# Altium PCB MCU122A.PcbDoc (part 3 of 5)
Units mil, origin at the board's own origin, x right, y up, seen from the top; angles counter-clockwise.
Board outline 4950 x 3450 mil, 4 copper layers (Top Layer, Signal Layer 1, Signal Layer 2, Bottom Layer), stack 60 mil thick; 257 components, 158 nets, 848 pads, 1971 vias.
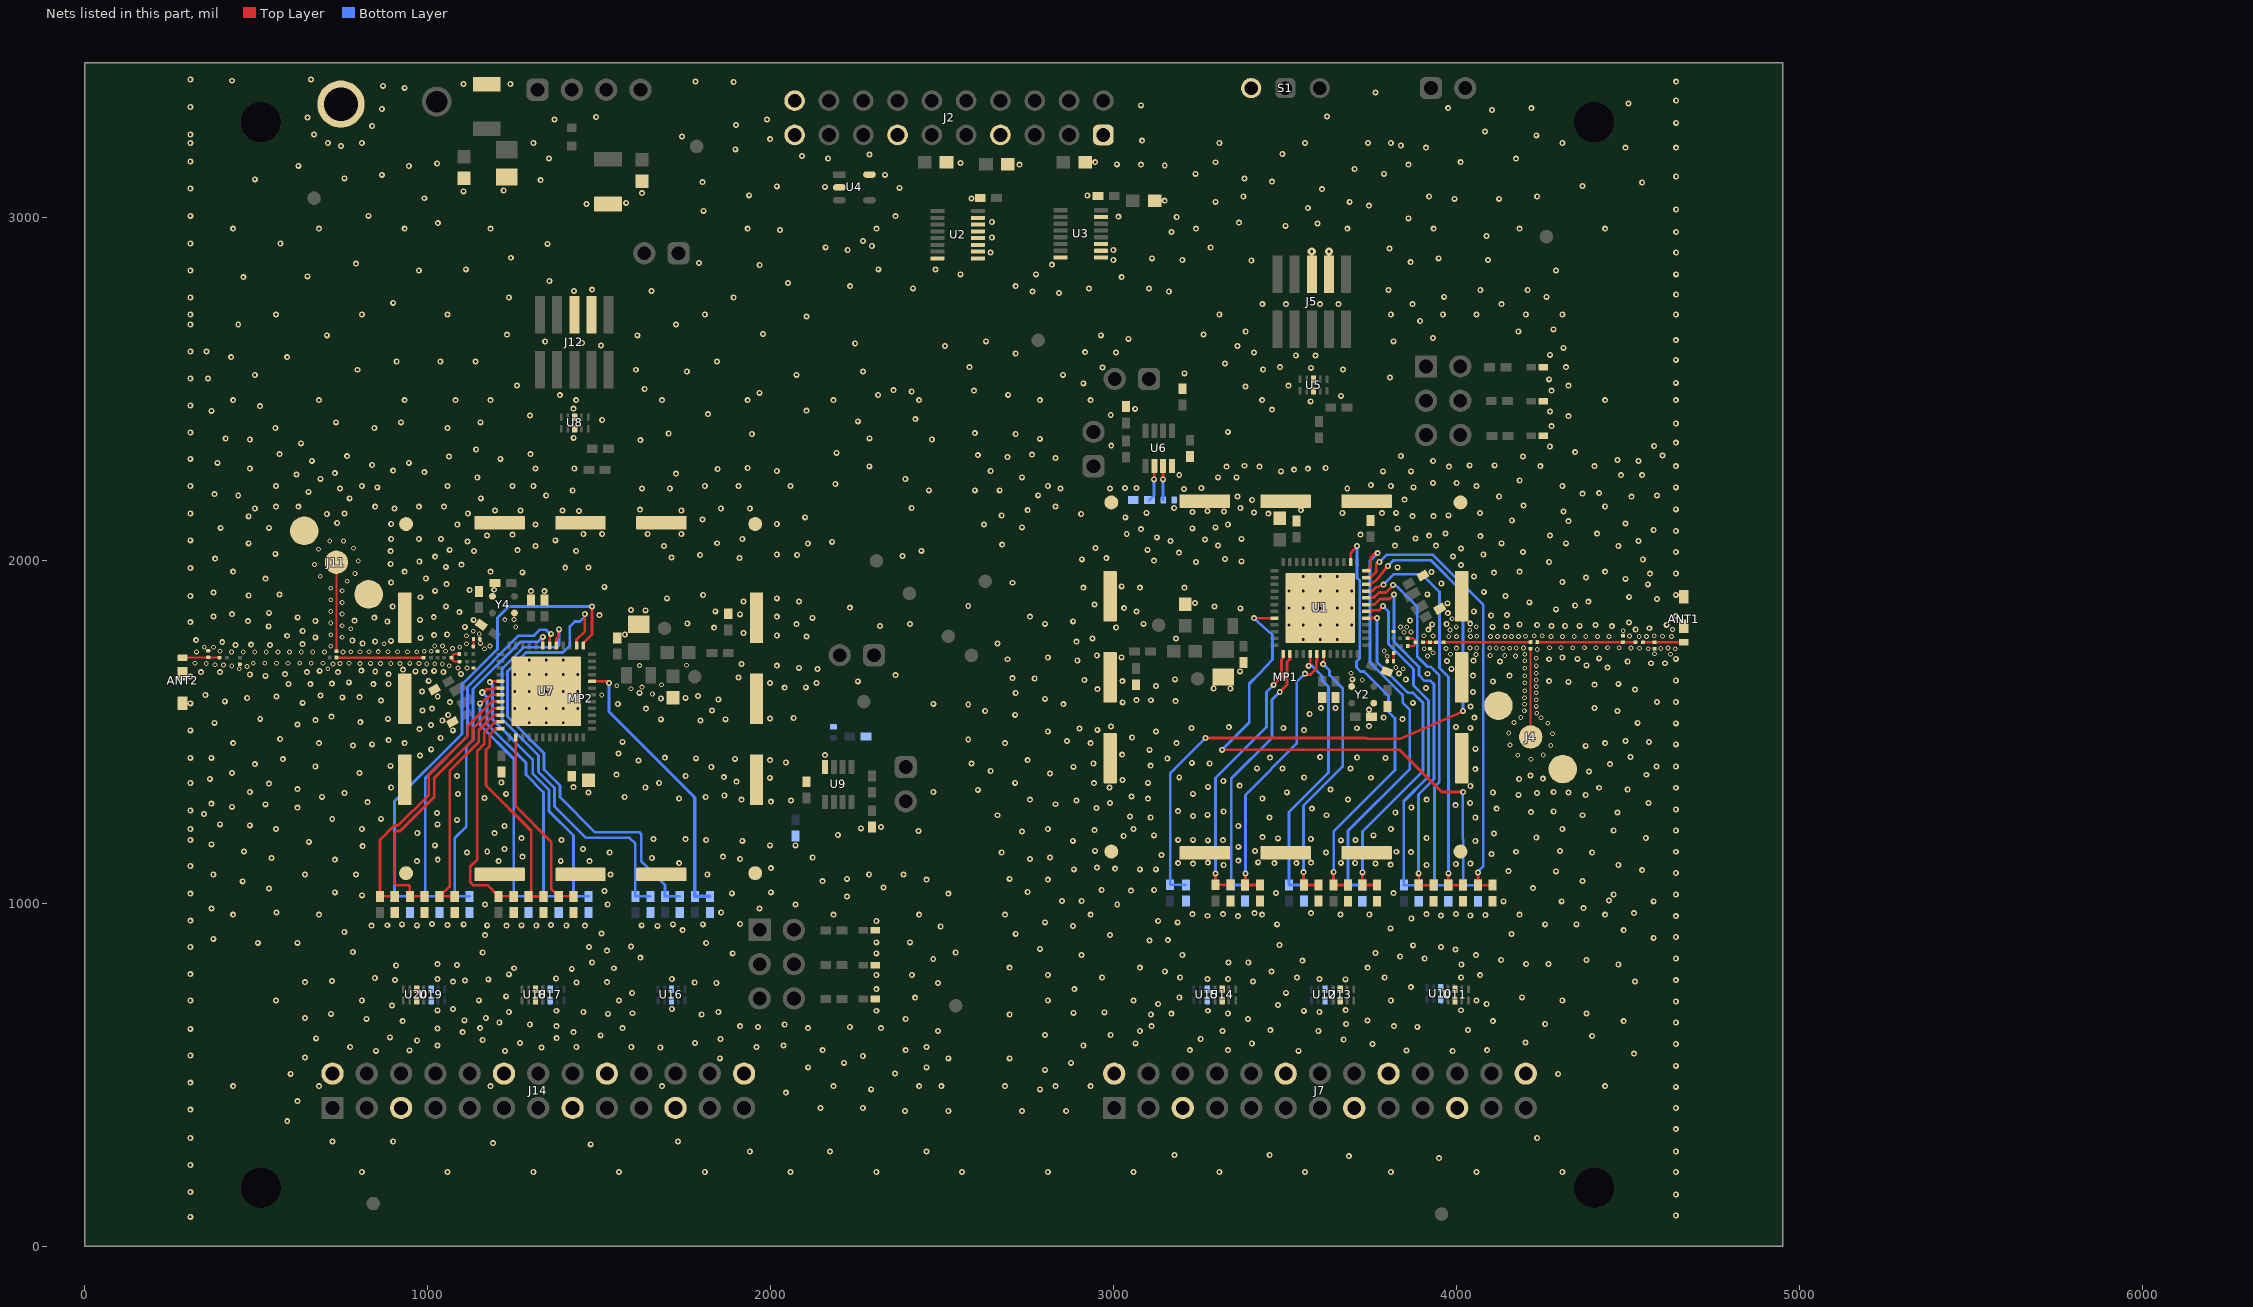
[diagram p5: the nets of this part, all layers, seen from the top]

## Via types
v1: diameter 17.46, hole 8, Top Layer to Bottom Layer, tented both sides, 1708 vias
v2: diameter 13.9, hole 8, Top Layer to Bottom Layer, tented both sides, 206 vias
v3: diameter 19.68, hole 8, Top Layer to Bottom Layer, tented both sides, 42 vias
v4: diameter 24, hole 8, Top Layer to Bottom Layer, tented both sides, 8 vias
v5: diameter 19.46, hole 8, Top Layer to Bottom Layer, tented both sides, 6 vias
v6: diameter 34, hole 8, Top Layer to Bottom Layer, tented both sides, 1 vias

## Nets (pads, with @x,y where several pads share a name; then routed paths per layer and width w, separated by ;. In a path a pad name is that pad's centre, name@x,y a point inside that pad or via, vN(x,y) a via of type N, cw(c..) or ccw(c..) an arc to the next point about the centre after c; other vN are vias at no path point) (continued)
GND: ANT1.2 ANT1.3 ANT2.2 ANT2.3 C1.1 C2.2 C3.2 C4.1 C5.2 C6.1 C7.1 C8.1 C9.1 C10.2 C11.2 C12.1 C13.1 C14.1 C15.1 C16.1 C17.2 C18.1 C19.1 C20.1 C21.2 C22.2 C23.2 C24.2 C25.2 C26.2 C27.2 C28.2 C29.1 C30.1 C31.1 C32.1 C33.1 C34.1 C35.2 C36.2 C37.2 C38.2 C40.2 C41.2 C44.1 C45.1 C46.1 C47.1 C48.2 C49.2 C50.2 C51.2 C52.1 C53.1 C54.1 C55.2 C56.1 C57.1 C58.1 C59.1 C60.1 C61.2 C62.2 C63.2 C64.2 C65.2 C66.2 C67.2 C68.2 C69.1 C70.1 C71.1 C72.1 C73.1 C74.1 C75.2 C76.2 C77.2 C78.2 C80.2 C81.2 C84.1 C85.1 C86.1 C87.1 C88.2 C89.2 C90.2 C91.2 D1.1 D2.1 D3.1 D4.1 D5.1 D6.1 J2.1 J2.7 J2.13 J2.19 J2.20 J4.2 J4.3 J5.3 J5.5 J7.2 J7.5 J7.12 J7.15 J7.18 J7.21 J7.26 J11.2 J11.3 J12.3 J12.5 J14.2 J14.5 J14.12 J14.15 J14.18 J14.21 J14.26 MP1.1 MP1.2 MP1.3 MP1.4 MP1.5 MP1.6 MP1.7 MP1.8 MP1.9 MP1.10 MP1.11 MP1.12 MP1.13 MP1.14 MP1.15 MP1.16 MP2.1 MP2.2 MP2.3 MP2.4 MP2.5 MP2.6 MP2.7 MP2.8 MP2.9 MP2.10 MP2.11 MP2.12 MP2.13 MP2.14 MP2.15 MP2.16 R23.1 R24.1 R47.1 R48.1 S1.2 TP3.1 U1.49 U2.8 U2.9 U2.10 U2.11 U2.12 U2.13 U2.14 U2.15 U3.8 U3.9 U3.10 U3.11 U3.15 U4.2 U4.5 U5.3@3582.66,2526.68 U5.8@3582.66,2493.81 U6.4 U7.49 U8.3@1428.4,2416.13 U8.8@1428.4,2383.26 U9.4 U10.3@3953,719.63 U10.8@3953,752.5 U11.3@3995.17,715.83 U11.8@3995.17,748.71 U12.3@3615.99,715.83 U12.8@3615.99,748.71 U13.3@3660.39,715.83 U13.8@3660.39,748.71 U14.3@3316.14,715.83 U14.8@3316.14,748.71 U15.3@3272.4,715.83 U15.8@3272.4,748.71 U16.3@1710.72,715.83 U16.8@1710.72,748.71 U17.3@1357.81,715.83 U17.8@1357.81,748.71 U18.3@1314.16,715.83 U18.8@1314.16,748.71 U19.3@1010.16,715.83 U19.8@1010.16,748.71 U20.3@967.76,715.83 U20.8@967.76,748.71 Y2.2 Y2.4 Y4.2 Y4.4 | length 1.1
  Top Layer w8: C62.2@1552.78,1773.13 C62.2@1553.55,1772.36
  other v1: 308,85.18 4638.91,88.8 4638.91,150.58 308,157.48 808,216 1058,216 1308,216 1558,216 1808,216 2058,216 2308,216 2558,216 2808,216 3058,216 3308,216 3558,216 3808,216 4058,216 4308,216 4638.91,216 308,236.22 3948.46,256.3 3685.58,262.14 3177.35,265.07 3454.83,265.07 1939,275.59 2173,275.59 2454.03,275.59 4638.91,275.59 1475.36,296.56 1190.05,300 722.44,305.12 899.44,305.12 1729.67,305.12 308,314.96 4234.7,314.72 4638.91,340.52 590.55,364.17 2391.73,393.7 2518.02,393.7 2732.98,393.7 2861.51,393.7 308,397.43 4638.91,402.22 2145.12,402.76 2268.53,402.76 620.23,422.44 2044.09,447 2293.05,456.89 2785.43,456.89 4638.91,464.06 433,466 683,466 1183,466 1683,466 2183,466 2433,466 2497.32,466 2683,466 2830.01,466 2933,466 4433,466 308,476.34 600.39,501.97 4296.04,501.66 2362.2,502.76 2799.9,513.67 2109.25,521.13 2454.03,521.13 4638.91,525.28 2213.73,534.3 2875.69,534.3 1851.64,547.34 2518.02,547.34 2696.85,547.34 641.93,549.99 2268.53,553.71 308,555.53 4516.84,560.63 1225.2,568.47 848.95,569.22 3538.57,569.23 3988.26,568.84 3853.57,569.8 946.84,570.62 2151.56,570.89 2393.7,570.89 3222.1,570.89 3333.33,570.89 4089.03,570.89 1332.14,579.17 1678.22,578.63 773.92,580.13 1433.42,580.05 1593.69,580.22 1958.5,580.22 2454.03,580.22 2037.4,584.34 2911.31,584.34 1028.41,584.6 3754.56,589.29 4638.91,589.1 3402.7,590.46 3063.77,590.93 1269.16,591.97 1779.02,591.97 4200.48,593.6 969.21,599.52 1160.15,600.66 3670.52,601.83 3253.58,603.26 1853.68,603.57 674.78,605.5 1376.2,606.07 889.97,608.37 4394.9,612.18 1504.39,614.31 2799.9,615.35 2991.23,615.35 1101.92,623.6 1425.04,623.6 2487.48,626.86 3076.34,626.91 3317.07,626.86 3596.65,626.91 3456.68,629.42 4032.88,630.07 308,633.38 1028.41,634.48 1152.98,635.18 1567.86,635.18 2108.89,635.18 2321.77,635.18 1962.92,638.88 2230.67,638.88 3885.11,639.31 1375.38,640.98 1911,640.98 3110.14,640.87 3817.13,640.87 1297.76,645.78 2040.95,645.78 3677.96,647.32 4258.11,647.32 1208.77,651.91 4638.91,652.02 4105.38,655.39 4486.77,655.39 927.15,655.71 1107.09,658.1 3740.33,657.79 821.93,662.43 2393.7,662.25 3391.47,662.25 641.93,665.05 1169.59,665.05 1798.83,675 2696.85,675 3108.34,675 718.2,676.9 1525.71,676.9 3167.94,677.43 3332.61,678.26 4378.35,678.26 1596.89,678.68 2882.5,680.04 2973.43,681.43 1236.41,682.23 1453.84,682.4 1847.22,682.4 3599.39,682.6 1374.96,685.99 2308,685.99 3274.46,685.99 3554.33,685.87 1028.76,687.32 4012.61,687.45 3676.52,687.76 1073.63,690.88 1711.57,690.86 895.78,701.06 3479.27,702.58 3129.77,705.44 4087.34,705.44 4638.91,712.92 308,716 558,716 808,716 1558,716 2808,716 3058,716 3808,716 4058,716 4308,716 1148.99,716.56 2421.26,724.03 3191.34,724.39 4190.69,725.22 1228.99,727.97 1596.35,737.87 3502.72,738.17 2308,748.71 2885.14,748.71 3866.16,754.7 1841.49,766.9 2487.48,766.9 1434.16,768.31 1778.29,768.31 641.93,769.23 1522.44,769.23 1073.63,770.59 3406.03,771.05 4519.73,771.05 721.1,772.86 1108.5,773.87 4638.91,775.16 904.33,775.59 1028.76,778.28 1176.59,777.69 1711.57,778.28 3273.25,778.23 3333.72,778.23 3676.09,777.51 3599.96,778.8 1374.61,780.34 845.93,781.78 2966.37,783.16 3193.75,782.73 3534.65,782.73 3790.19,782.73 4013.19,783 2308,790.08 2411.42,790.08 2808,790.08 4068.46,789.63 308,792.47 1236.41,792.32 3149.04,800.44 3460.45,800.44 1419.99,808.32 1252.18,809.88 1542.65,809.88 2696.85,811.6 3076.34,811.6 3740.57,811.6 908.09,817.99 1085.3,819.6 4013.67,820.56 4471.38,820.56 1028.46,821.8 4202.54,822.39 4267.89,822.39 1479.43,826.68 3334.42,826.62 3392.35,826.62 3549.98,831.8 4129.9,833.82 4378.35,833.82 2473.93,836.5 3906.67,838.35 4638.91,838.2 1619.93,840.52 3835.25,844.38 2905.86,848.25 3199.93,848.25 4056.53,848.01 1889.27,853.51 2308,853.51 3763.58,854.36 1160.16,855.45 2539.37,855.61 781.81,857.02 1522.44,860.94 3996.34,864.86 2785.43,866.48 1470.01,871.5 308,871.7 3954.3,871.92 1592.96,873.01 3483.44,877.44 3873.04,876.71 1812.03,883.17 504.77,884.1 620.23,884.1 2308,885.41 2406.31,885.41 3104.36,891.05 3157.68,891.68 374.82,895.67 4574.18,898.76 4638.91,900.98 1167.27,906.27 2989.33,906.78 2714.34,910.22 4159.92,909.95 1506.38,911.2 756.81,915.47 1743.25,920.8 4486.77,920.82 3806.99,926.27 2495.69,931.39 2881.5,932.9 835.95,933.9 1229.71,933.84 1458.33,934.14 1670.21,933.72 882.45,935.26 968.95,934.92 1173.53,934.92 1273.75,935.2 1316.7,934.56 1404.05,934.56 1624.01,935.04 1057.98,935.67 1359.66,935.92 925.32,937.86 1104.83,938.13 1715.04,938.13 1802.28,938.13 3476.55,938.07 4258.11,938.07 4349.5,938.07 1012.77,939.14 1911,938.55 2799.49,943.63 3186.48,943.63 308,948.45 2308,947.8 3129.77,947.8 3867.79,955 3362.39,961.82 4638.91,961.78 3273.49,962.95 3954.07,963.62 4039.64,963.62 4083.36,964.87 433,966 683,966 2183,966 2433,966 2683,966 2933,966 3433,966 3661.08,966.49 3745.33,966.49 4183,966 4433,966 3229.59,967.39 3318.53,967.39 3912.09,967.39 3997.7,967.92 3410.68,970.45 3575.37,970.47 4516.84,970.45 558.88,972.2 1855.53,972.2 369.39,984.01 1967.72,984.25 4369.79,985.17 2072.01,995.4 3010.4,995.4 1166.97,995.82 1524.68,995.82 4136.25,1005.16 4306.05,1004.98 4574.18,1004.98 2849.54,1005.95 2906.58,1005.95 4444.16,1007.5 2222.16,1019.14 808.23,1022.63 4457.81,1024.73 4638.91,1024.91 308,1027.25 2518.02,1027.25 1886.65,1028.42 3473.21,1029.16 3815.85,1028.6 729.36,1031.19 2000.39,1031.24 2749.24,1032.07 1515.22,1035.2 3050.19,1035.97 2965.11,1038.31 3117.95,1038.31 537.1,1042.38 4222.44,1043.31 2328.6,1045.03 460.66,1063.31 2151.14,1063.59 4366.63,1064.33 2454.03,1067.98 2808,1067.98 2222.16,1070.68 2696.85,1070.68 374.82,1083.5 641.93,1083.5 790.7,1083.5 1532.84,1083.5 1815.27,1083.5 2287.19,1083.5 2386.9,1083.5 4638.91,1087.36 4289.24,1092.48 4151.36,1092.79 4540.72,1095.96 2883.68,1098.28 3076.01,1098.28 3122.86,1098.28 3004.42,1100.05 2000.39,1101.76 2951.39,1103.58 308,1107.92 3320.51,1110.9 3912.6,1111.03 4471.38,1111.03 3807.43,1111.98 3997.29,1113.52 3231.24,1114.6 3763.5,1115.16 4039.64,1115.46 1733.13,1116.34 3188.12,1116.36 3468.25,1116.36 3532.33,1116.36 3662.17,1117.42 3704.1,1116.6 3274.35,1117.73 3575.33,1117.73 3421.3,1118.6 969.1,1121.98 1206.97,1121.98 1471.73,1121.98 1387.91,1123.08 3363.3,1123.34 729.36,1126.47 1029.31,1126.47 1911,1128.09 2755.93,1128.09 544.79,1131 1653.39,1131 2122.4,1132.69 2814.22,1132.69 1276.68,1135.03 1860.98,1135.03 3139.65,1139.82 4101.31,1142.68 1114.46,1147.48 1530.45,1147.3 2673.48,1147.13 3619.22,1147.13 4394.9,1147.13 3866.93,1148.12 464.51,1150.5 1173.63,1150.5 3823.99,1149.55 4173.42,1149.55 4638.91,1149.55 2945.2,1152.2 3412.08,1151.96 4301.18,1151.57 1223.84,1157.72 1452.73,1157.72 3363.19,1163.94 810.52,1165.81 1020.68,1168.18 1998.03,1168.18 2072.01,1168.18 369.39,1171.26 653.25,1178.32 4054.16,1180.83 1917.13,1181.51 2880.95,1181.51 3274.35,1182.84 3318.48,1183.28 3662.17,1182.72 3704.68,1183.45 308,1184.06 1390.19,1184.06 1812.03,1184.06 3188.12,1184.45 3231.1,1184.45 1751.96,1186.09 1658.63,1186.88 3574.89,1186.62 1273.75,1189.13 3479.23,1188.82 3912.6,1189.36 4551.56,1189.36 4232.28,1190.94 3433.59,1191.89 3029.17,1195.51 3117.55,1197.27 3757.77,1197.31 2195.6,1198.36 4108.64,1202.56 969.81,1204.49 1194.86,1203.68 2732.98,1208.51 2431.03,1209.85 4457.81,1211.16 4638.91,1211.16 2944.32,1212.3 308,1216 558,1216 808,1216 2808,1216 3058,1216 3808,1216 4308,1216 2263.23,1217.89 2321.77,1221.74 3363.2,1224.32 1223.84,1224.76 481.39,1226.58 394.11,1229.49 1028.52,1229.49 1085.19,1242.75 721.72,1245.36 863.6,1245.41 3107.75,1249.33 3454.21,1249.38 4054.16,1249.38 3047.73,1252.07 3231.28,1253.52 2661.34,1255.96 3620.09,1255.96 4366.63,1255.96 3273.5,1257.04 347.69,1259.84 1026.84,1262.44 3821.08,1263.86 4469.11,1263.86 4216.54,1265 3320.51,1266.59 4282.64,1266.59 3187.3,1267.69 308,1269.69 4638.91,1273.03 3577.53,1275.27 4116.5,1275.27 2949.62,1276.82 620.23,1277.89 3867.76,1278.2 429.59,1280.62 3996.74,1285.12 527.42,1287.97 2830.01,1288.01 369.33,1289.61 2989.39,1291.85 4039.33,1291.82 4559.29,1292 824.55,1293.94 2000.39,1295.44 2058.89,1299.24 2891.53,1299.24 1914.95,1301.5 2755.93,1301.5 3912.44,1301.46 3682.98,1301.53 3099.88,1304.22 1733.29,1304.86 3433.15,1304.67 1165.31,1306.07 1574.19,1309 1810.3,1308.83 691.91,1309.62 3051.92,1310.56 1864.84,1313.36 4180.36,1315.46 4376.27,1315.19 1088.42,1317.63 3231.07,1318.41 1228.75,1318.58 757.62,1320.49 4234.43,1320.71 1468.56,1322.32 4105.26,1322.02 4325.74,1322.02 2474.2,1323.46 3504.61,1322.88 481.39,1323.87 4282.64,1324.02 2604.02,1330.07 3631.94,1331 4498.59,1331 620.23,1332.04 4415.39,1336.12 4638.91,1336.12 893.56,1336.57 1634.6,1336.57 2987.63,1336.92 1425.04,1337.71 3274.96,1338.97 4039.68,1341 3367.45,1342.21 537.1,1347.92 2942.55,1349.3 308,1350.26 1674.73,1350.26 2712.79,1350.5 3099.88,1350.5 1214.77,1351.53 1900.22,1353.69 3319.5,1355.74 3025.63,1359.02 364.77,1362.19 4182.35,1361.79 4250.97,1362.41 1997.41,1365.06 3749.81,1365.28 3555.28,1365.96 1863.24,1366.82 3191.14,1366.58 1085.19,1370.25 1752.32,1370.25 4215.42,1371.81 1550.35,1374.32 4552.78,1374.02 2814.22,1378 429.59,1378.78 801.31,1378.78 4385.82,1383.2 2641.37,1384.89 4054.16,1390.36 3491.95,1392 3690.75,1392.44 3417.48,1392.69 1827.07,1396.39 2882.5,1397 672.44,1398.02 4582.23,1397.97 4638.91,1397.97 891.72,1400 3107.83,1400.56 495.96,1404.81 4446.85,1404.84 2585.19,1406.75 2940.78,1406.75 3279.9,1406.75 3227.8,1408.67 2044.09,1409.62 1614.68,1415.69 1998.03,1416.62 2749.24,1416.62 577.44,1419.52 1895.9,1420.5 1781.96,1422.04 3156.44,1421.66 308,1423.4 369.33,1423.4 3792.6,1422.57 1691.25,1423.95 3455.88,1423.63 3709.96,1424.32 3602.17,1425.34 4506.68,1425.5 977.47,1430.16 2158.46,1430.96 3024.75,1432.38 1556.16,1435.88 3104.36,1446.8 1010.16,1448 4054.72,1449.62 4376.27,1458.38 782.51,1459.58 838.02,1462.7 4638.91,1462.63 433,1466 683,1466 933,1466 2683,1466 2933,1466 3183,1466 4433,1466 4561.01,1469.17 1567.72,1470.06 2863.86,1472.41 4492.44,1472.44 886.25,1474.68 2575.97,1476.96 569.76,1478.39 1037.94,1481.39 3053.92,1482.76 2808,1500.17 3123.23,1500.17 308,1503.65 1073.39,1503.65 3554.71,1503.91 2952.27,1504.86 976.25,1506.8 2900.31,1508.75 3227.15,1510.16 3494.58,1510.49 3708.74,1509.61 4039.68,1510.83 3335.82,1512.83 3997.91,1513.43 2992.04,1514.58 3744.7,1515.72 1009.48,1519.31 620.23,1520.78 4638.91,1523.85 378.17,1525.35 4527.56,1525.59 803.54,1527.38 1042.59,1531.98 1795.15,1531.98 672.71,1533.05 1679.73,1535.53 1867.92,1535.79 3842.18,1536.1 511.81,1536.96 883.94,1536.96 1998.03,1538.33 2066.93,1539.25 4051.23,1540.26 3787.24,1541 719.66,1543.4 1059.71,1547.98 2712.79,1548.74 3571.38,1551.3 2625.43,1560.03 4469.11,1560.03 985,1561.57 1828.91,1561.57 3744.06,1563.83 1012.77,1566.74 1636.51,1566.74 3603.83,1568 4401.76,1568.37 3647,1568.8 4040.5,1573.04 2575.97,1578.66 1554.3,1580 2853.04,1579.71 2474.2,1580.95 308,1582.46 635.38,1583.71 3871.99,1583.75 3026.39,1585.22 1064.72,1585.53 4583.97,1586.33 4638.91,1586.33 408.46,1588.23 3180.17,1588.42 863.6,1590.31 3108.34,1591.24 3066.86,1591.59 1847.22,1593.38 2799.9,1595.5 1679.82,1596.61 473.81,1597.91 1751.5,1598.48 750.99,1599.73 801.31,1600.1 558.87,1602.08 1029.31,1601.94 1788.37,1603.72 687.52,1605.05 351.54,1606.37 2714.34,1612.32 1617.5,1612.75 4047.64,1615.37 983.14,1616.88 4519.73,1622.25 2953,1623.52 3291.36,1625.18 3339.9,1625.18 3910.49,1627.18 2040.95,1627.98 2102.54,1628.89 3123.23,1632.45 4401.49,1636.78 657.66,1638.2 841.28,1638.2 594.24,1638.89 886.25,1638.89 4471.38,1639.08 720.56,1639.62 1998.03,1641.5 2133.35,1641.5 769.93,1643.46 4325.74,1645 2254.09,1646.49 4105.26,1646 3025.33,1646.92 4269.69,1646.72 1003.05,1648.03 4638.91,1649.06 2914.5,1650.41 3851.64,1651.49 3178.61,1652.21 3695.87,1652.21 2769.61,1654.86 2705.08,1655.5 1906.42,1657.44 308,1660.73 527.42,1662.55 4047.64,1663 4153.96,1663 2364.12,1664.38 481.39,1666.49 584.15,1667.09 886.25,1667.09 1097.3,1667.94 3915.03,1668.49 3831.53,1669.52 338.87,1673.05 394.11,1673.05 648.07,1673.17 738.64,1673.17 991.11,1674.4 1045.69,1673.85 847.11,1675.22 964.28,1675.48 3368.45,1675.73 685.19,1677.19 806.46,1677.37 1019.05,1677.19 928.03,1680.34 2136.21,1682.06 3984.72,1682.76 2082.68,1685.78 4439.92,1686.44 2017.72,1692.11 4378.35,1693.03 1914.95,1697.14 4566.6,1699.11 4607.45,1699.11 4126.34,1704.16 4498.59,1704.07 3971.96,1705.81 2894.07,1707.03 4048.77,1706.57 2690.71,1710.77 4269.69,1710.77 4352.48,1711.96 4638.91,1711.96 4415.39,1713.41 2808,1716 3022.91,1716.31 4308,1716 2950.86,1721.39 439.57,1752.31 540.52,1752.31 485.22,1753.33 634.88,1754.85 810.34,1756.65 2661.34,1756.84 401.01,1760.43 2891.53,1762.03 846.77,1762.85 892.79,1764.44 780.3,1765.19 325.03,1766.45 2938.09,1771.39 3182.02,1771.45 979.24,1773.43 672.44,1774.86 2104.33,1777.25 590.33,1779.3 2017.72,1779.66 1018.83,1780.92 1056.76,1783.23 1574.82,1783.25 1920.43,1787.08 635.38,1793.32 3917.29,1796.79 4521.89,1797.35 4561.64,1801.15 1835.16,1802.67 3007.24,1803.31 1108.35,1805.49 4104.69,1805.41 4145.31,1805.84 536.23,1806.68 4316.37,1807.46 4452.27,1807.24 2318.9,1807.98 4276.68,1807.96 4358.22,1808.29 4234.77,1810.63 4404.74,1810.51 4612.42,1811.02 3928.66,1812.32 4183.5,1812.32 2074.9,1812.87 3970.74,1813.28 2406.31,1813.67 2799.49,1814.11 3086.9,1814.11 4039.53,1814.39 1756.87,1814.87 4502.07,1817.64 308,1818.79 882.45,1820.95 2881.95,1821.3 475.75,1821.76 672.44,1822.5 786.39,1823.31 3864.6,1823.4 977.47,1825.66 1134.23,1825.77 844.24,1831.99 2121.58,1831.5 621.03,1833 1017.65,1833.36 2017.72,1834.98 2755.93,1834.99 375.81,1835.61 4638.91,1836.3 4100.46,1838.43 1501.07,1839.23 4146.82,1839.48 429.59,1842.21 1910.87,1841.92 3974.07,1845.17 537.1,1846.22 1092.33,1847.86 3066.86,1849.76 4050,1850.23 1838.52,1850.66 1634.95,1853.26 1592.96,1854.42 4289.24,1856.3 3369.21,1859.29 3030.65,1859.69 2230.67,1861.13 3293.64,1864.3 897.87,1864.86 1053.65,1864.86 2575.97,1866.1 4345.55,1867.13 2944.32,1870.08 3973.49,1873.74 3237.09,1875 4211.84,1876.82 1920.87,1878.81 2082.68,1878.81 4383.85,1878.54 4583.97,1886.35 1697.45,1888.49 2017.72,1888.28 978.45,1891.54 4502.84,1892.72 308,1895.01 4142.15,1895.46 478.12,1896.81 1803.32,1897.78 4638.91,1898.5 567.83,1899.71 3914.43,1899.94 375.81,1905.12 4078.98,1907.4 1301,1909.21 1340,1909.21 1021.66,1910.27 1122.5,1912.54 1193.79,1913.4 2911.5,1919.27 3076.01,1919.27 3206.18,1919.27 1514.84,1921.78 3023.2,1923.52 4557.09,1929.13 1054.9,1929.53 3955.05,1931.27 2705.08,1933.82 893.56,1934.51 4308,1935.83 527.42,1945.5 4492.44,1945.27 994.67,1946.51 4377.01,1948.82 4050.7,1951.71 4563.26,1960.29 4638.91,1960.98 4108.64,1963.16 1275.84,1964.05 3926.39,1965.29 433,1966 933,1966 1183,1966 4183,1966 4433,1966 308,1976.66 1401.05,1977.79 1468.97,1978.09 3827.66,1978.82 1052.76,1980.26 4012.38,1985.48 1098.36,1986.58 892.15,1988.32 3240.05,1994.23 4269.69,1994.59 975.67,1995.81 3372.7,1996.19 3117.88,1997.99 2907.11,2002.2 4542.8,2001.72 3324.69,2003.16 380.31,2003.84 2978.52,2005.44 1909.24,2006.22 1710.54,2007.19 1021.97,2009.71 3989.59,2010.48 2384.43,2012.03 1794.52,2014.78 2077.12,2014.78 2017.72,2016.3 4077.67,2015.9 555.76,2018.1 3190.22,2021.39 4193.5,2023.15 4638.91,2023.4 891.96,2025.72 1135.02,2026.28 1432.89,2026.28 2439.25,2026.91 1261.99,2028.81 1064.08,2029.97 3098.36,2029.97 4012.38,2033.74 2947.01,2034.96 1313.98,2040.69 1688.77,2040.69 4471.38,2040.79 3304.15,2042.32 3820.35,2041.78 3940.04,2041.78 2675.05,2044.73 2108.07,2048.2 478.12,2048.85 1844,2048.96 4130.84,2048.83 4318.48,2048.83 2179.22,2053.13 1115.9,2054.01 3165.67,2055.78 4530.05,2055.71 308,2057.37 1372.04,2057.37 3266.53,2060.01 893.56,2061 973.99,2061 1039.1,2061 1917.11,2061 3372.66,2061.91 3879.77,2063.15 3125.68,2066.38 4069.04,2069.67 3919.78,2071.18 4272.37,2071.3 1172.58,2071.88 1247.47,2073.85 3719.48,2073.89 1453.84,2075.77 1508.87,2075.77 1641.4,2075.77 1739.52,2075.77 3038.09,2075.65 3967.24,2077.18 4409.45,2076.77 4638.91,2085.01 4574.18,2087.79 3079.49,2090 3229.35,2092.67 3827.78,2092.67 396.59,2093.88 537.1,2093.88 2732.98,2095.56 3296.82,2095.56 1086.36,2103.84 1313.98,2103.84 2621.9,2103.78 3332.74,2103.78 893.56,2104.97 2017.72,2104.97 4492.44,2106.48 736,2107.73 4325.74,2113.19 4160.64,2115.16 1801.18,2118.52 2100.65,2124.59 3033.84,2124.59 478.12,2127.5 3871.42,2127.71 3932.23,2127.71 2673.48,2130.22 3976.45,2130.47 705.92,2134.19 308,2135.42 2905.27,2134.55 3450.95,2135.04 757.62,2136.03 1117.13,2136.03 3666.39,2137.18 3782.11,2136.53 4067.65,2137.38 3095.49,2137.62 3409.04,2138.44 3823.63,2137.77 3230.11,2140.05 3321.52,2141.4 4311.25,2141.4 1441.4,2143 3273.36,2142.8 1195.97,2144.34 1270.65,2144.34 1392.91,2144.34 1739.52,2144.34 2749.24,2145.21 3545.43,2145.21 1618.87,2146.94 4638.91,2147.97 495.96,2150.19 903.45,2150.19 1854.58,2150.19 1939,2150.19 2410.9,2151.85 3176.37,2151.85 3369.21,2151.85 558,2155.51 622.9,2155.51 846.89,2155.51 973.99,2155.51 1047.6,2155.51 2830.01,2156 4433,2156 4194.64,2158.91 3403.91,2175.16 3848.14,2175.9 772.45,2180.05 1154.94,2180.06 3361.31,2185.12 4124.02,2185.04 4509.41,2184.71 447.69,2188.32 1345.58,2188.32 4584.26,2188.02 2779.81,2188.71 378.17,2191.99 4366.63,2193.64 4415.39,2195 652.52,2198.98 1422.75,2202.61 2461.25,2203.29 2595.19,2203.29 2667.64,2203.29 3204.89,2207.03 744.05,2208.45 1624.51,2208.45 1705.88,2208.45 2844.77,2208.7 2989.5,2208.7 3680.96,2208.7 3032.9,2209.91 3066.86,2209.91 3255.54,2209.91 853.06,2211.94 3874.19,2212 4638.91,2212 308,2216 558,2216 808,2216 1058,2216 1247.47,2216 1308,2216 1808,2216 1906.42,2216 2058,2216 2808,2216 3808,2216 4058,2216 4308,2216 3749.76,2218.58 2188.32,2221.48 3930.85,2224.44 3999.94,2224.44 4183.5,2232.24 2392.35,2236.25 687.24,2236.86 1144.71,2240.64 2732.98,2241.29 3304.15,2241.29 3358.32,2241.29 4478.95,2247.33 4540.72,2247.33 3191.14,2248.05 617.44,2249.11 1724.17,2251.92 729.36,2253.38 990.27,2256.27 3487.48,2258.53 3785.12,2258.53 3867.14,2258.53 899.5,2260.49 2017.72,2259.63 2641.37,2259.63 3526.06,2263.59 1845.28,2265.16 3565.89,2266.22 481.39,2267.16 1313.98,2267.16 1427.57,2267.16 1933.06,2268.54 3617.91,2268.51 3329.11,2272.2 3425.15,2272.2 3977.77,2272.2 2287.67,2273.14 4243.67,2273.62 4401.49,2273.62 4638.91,2273.62 3381.34,2274.91 4037.94,2276.35 4110.65,2276.35 838.02,2277 387.17,2283.46 944.96,2283.46 662.06,2289.36 3931.38,2288.92 4529.99,2288.92 4469.11,2291.63 308,2295.06 1211.72,2295.06 2830.01,2297.65 2690.71,2300.52 1062.06,2301.6 4193.5,2301.94 765.13,2302.85 3837.19,2303.17 4600.37,2304.76 2604.02,2305.82 2761.49,2307.22 567.68,2308.58 1299.91,2308.58 2191.79,2312.52 4345.34,2314.42 1141.44,2322.27 4271.56,2331.07 2992.88,2333.27 4575.76,2332.65 630.6,2340.16 4638.91,2341.99 1619.93,2349.56 481.39,2351.41 2469.88,2351.13 2784.57,2353.3 411.13,2354.52 2288.09,2354.78 1425.61,2356.26 1944.97,2367.28 2714.34,2367.64 1702.59,2369.13 2595.19,2369.75 308,2372.05 3332.74,2373.94 555.76,2385.03 844.24,2385.03 1057.58,2385.03 4276.41,2390.35 4638.91,2397.82 733,2401.57 922.1,2401.57 1153.95,2401.57 2253.84,2404.53 1508.87,2408.55 2421.68,2410.69 4325.74,2419.47 1298,2421.35 2991.42,2423.14 1817,2425.29 4272.37,2433.17 369.39,2435.23 2104.59,2435.4 3461.81,2438.4 1425.06,2441.46 3062.74,2440.81 511.12,2448.42 308,2450.79 3574.5,2462.71 433,2466 683,2466 933,2466 1081.14,2466 1183,2466 1433,2466 1683,2466 1933,2466 2183,2466 2433,2466 2784.57,2466.16 2933,2466 3433,2466 4433,2466 4638.91,2466 3663.02,2478.86 1385.16,2480.53 2313.45,2480.98 2692.38,2481.69 1967.45,2487.49 2410.9,2491.39 2592.72,2493.81 4276.79,2493.81 2358.27,2495.22 1632.7,2498.89 3384.36,2506.25 3509.51,2508.43 4325.74,2508.43 1260.3,2509.09 2911.5,2515.29 4638.91,2516.74 4269.69,2526.96 308,2529.53 359.77,2529.53 3805.79,2532.25 495.96,2539.37 2074.9,2539.94 2852.53,2539.94 3206.77,2544.51 1755.32,2549.54 2269.3,2549.54 795.29,2554.79 1606.83,2554.79 3436,2555.76 3668.31,2555.76 2967.08,2561.29 3575.24,2560.55 2579.86,2562.21 3485.16,2562.21 4318.48,2562.21 3324.69,2573.28 909.68,2578.74 1036.74,2578.74 1139.53,2578.74 1843.49,2578.74 4638.91,2583.84 427.04,2591.27 590.33,2591.27 3531.11,2596.34 3588.39,2596.34 4272.37,2598.4 2714.34,2602.03 3006.78,2605.12 3408.97,2605.12 2917.03,2606.16 308,2608.27 354.77,2608.27 4311.25,2618.65 2508.06,2623.98 3361.31,2623.98 1505.34,2625.62 2246.48,2631.59 1450.31,2633.11 1342.64,2636.86 2627.72,2637.76 3815.93,2637.76 4638.91,2641.06 3042.88,2644.94 3930.85,2647.65 705.92,2655.17 1611.13,2655.17 2962.56,2655.17 1231.26,2656.93 3261.76,2657.48 1977.5,2659.28 3384.78,2666.26 4179.58,2666.26 4282.43,2672.64 308,2687.01 447.69,2687.01 1724.17,2687.01 3893.67,2696.85 2104.33,2709.73 308,2716 558,2716 808,2716 1058,2716 1808,2716 3308,2716 3808,2716 3959.55,2716 4058,2716 4201.54,2716 4308,2716 4638.91,2716 3433.17,2746.06 3502.16,2746.06 3601.78,2746.06 3655.26,2746.06 3870.9,2746.06 4130.84,2746.06 899.5,2749.98 308,2765.75 1236.36,2765.75 1892.14,2765.75 3963.63,2767.57 4261.81,2767.57 4639.9,2773.95 2840.91,2778.53 2763.33,2782.63 3160.62,2782.63 1426.45,2784.29 1652.78,2784.33 3801.12,2787.32 4069.04,2787.32 4207.11,2787.32 1479.49,2788.07 2415.24,2792.06 2928.01,2791.8 3103.15,2791.8 2231.76,2798.34 2714.34,2798.34 2050.39,2807.83 1354.59,2813.8 462.6,2824.8 3023.2,2824.8 649.61,2827.32 2553.35,2832.87 2773.31,2832.87 4639.9,2832.87 308,2844.49 973.99,2844.49 4289.24,2844.49 1111.24,2847.47 2313.83,2847.47 2480.73,2847.35 1968.07,2859.89 2819.77,2861.24 790.84,2864.17 1791,2865.84 3865.87,2868.29 3401.12,2873.34 2998.9,2874.79 3200.1,2874.79 4091.53,2874.79 3111.45,2879.62 3947.5,2879.62 1242.41,2881.33 4639.9,2896.37 2640.52,2896.96 2224.41,2904.12 2998.9,2904.12 3803.82,2908.28 2160.33,2911.91 3282.79,2911.52 2295,2915.76 1349.36,2922 308,2923.23 570.25,2923.23 2269.3,2929.97 2644.51,2940.22 4086.66,2944.77 4639.9,2956.16 3168.86,2956.75 2027.43,2961.98 433,2966 683,2966 933,2966 1183,2966 1933,2966 2308.43,2966 3240.05,2966 3681.11,2965.91 3933,2966 4183,2966 4433,2966 3500.9,2974.37 3593.96,2981.41 1029.41,2982.28 3365.1,2983.4 2644.51,2985.31 3859.8,2996.2 3183.77,3000.18 3013.67,3001.09 2364.12,3002.69 308,3003.71 827.7,3003.71 1803.86,3018.12 4639.9,3021.65 3565.89,3026.59 3744.06,3033.12 1463.22,3037.82 1578.74,3041.55 3296.82,3044.33 3688.05,3044.33 3148.63,3047.58 3993.37,3053.31 4124.02,3053.31 2585.25,3054.21 990.27,3054.8 3378.01,3059.74 3919.78,3059.74 4234.77,3059.74 1937.31,3063.36 2923.01,3063.08 1624.51,3069.68 1104.34,3075.02 1221.45,3077.73 3607.55,3081.31 308,3083.41 2375.74,3085.18 2158.07,3088.06 2017.72,3089.47 4366.63,3090.55 4540.72,3100.39 1801.18,3101.59 3461.81,3103.06 1329.47,3107.64 495.96,3109.99 3381.34,3112.46 757.62,3112.94 4639.9,3118.47 866.14,3123.07 2333.59,3123.07 3238.74,3125.99 3787.79,3125.99 3702.56,3140.32 622.9,3149.49 944.96,3148.84 3148.86,3150.36 2725.1,3152.58 3079.49,3152.58 3859.8,3152.58 3009.09,3153.84 1027.77,3155.91 2553.35,3157.69 2946.15,3160 3296.82,3159.76 4011.63,3159.86 308,3162.02 1353.33,3170.43 4172.91,3170.2 2167.53,3170.7 2091.45,3178.3 2287.98,3182.11 3491.52,3184.01 1896.8,3197.59 3910.73,3202.24 4492,3202.24 4639.9,3202.24 747.05,3207.26 3837.19,3208.76 308,3216 708.66,3216 808,3216 1308,3216 3308,3216 3558,3216 3741.72,3216 3808,3216 4308,3216 3082.94,3222.68 1998.54,3227.08 1741.58,3234.78 4232.19,3238.19 308,3240.54 668.63,3240.54 4082.23,3249.32 838.02,3265.45 1899.14,3268.52 4639.9,3274.82 1989.01,3284.26 1369.37,3284.55 649.61,3290.47 1491.34,3291.35 3622.03,3293.2 4102.72,3312.32 866.14,3314.9 3975.12,3317.48 4217.42,3317.48 308,3320.99 3079.49,3325.58 4501,3331.33 4639.9,3340.03 3763.14,3363.23 933,3376.75 869.9,3382.74 1104.34,3388 1241,3388.16 1892.14,3393.39 1780.64,3394.94 4639.9,3394.63 429.18,3397.39 308,3401 659.45,3401
  other v2: 4216.71,1419.39 4178.19,1430.98 4252.22,1431.6 4274.27,1459.24 4155.47,1460.72 4279.05,1493.46 4151.96,1495.72 4265.22,1523.87 4167.06,1526.28 4245.93,1540.1 4186.82,1541.26 4233.24,1553.33 4197.35,1560.86 4232.28,1573.38 4197.46,1579.41 4232.28,1592.68 4197.99,1598.8 1507.14,1606.2 1655.04,1609.53 4232.28,1612.88 4198.2,1619.13 1592.68,1624.51 1624.79,1629.5 4232.28,1631.36 1550.97,1633.19 1681.72,1636.58 4198.13,1642.45 3724.55,1649.99 4232.28,1650.62 4198.58,1662.62 3691.95,1670.28 4232.28,1670.27 450.33,1682.97 708.63,1682.97 3844.26,1682.95 4198.13,1684.36 1088.04,1685.02 1114.87,1685.53 3822.04,1687.01 473.21,1689.45 428.79,1691.19 4232.28,1691.47 1062.79,1691.66 1617.83,1692.69 1754.68,1693.03 404.34,1693.69 379.81,1694.64 723.58,1697.06 997.38,1697.14 1020.27,1697.34 1042.59,1697.09 354.68,1698.21 744.14,1698.05 862.17,1698.5 892.39,1698.24 919.52,1698.24 321.6,1699.25 491.1,1698.79 525,1698.79 558.9,1698.79 592.8,1698.79 626.7,1698.79 660.6,1698.79 694.5,1698.79 770.23,1698.79 802.9,1698.64 832.98,1698.76 947.93,1698.76 974.47,1698.64 4198.12,1706.15 4232.28,1713.92 3797.71,1719.28 3914.7,1720.22 4171.31,1720 4097.51,1721.79 4139.87,1721.57 3981.99,1725.07 4056.11,1724.58 4198.56,1725.26 4623.66,1725.66 4576.61,1726.78 3930.79,1729.91 326.19,1732.28 427.89,1731.81 462.11,1732.15 495.69,1731.81 529.59,1731.81 563.49,1731.81 597.39,1731.81 631.29,1731.81 665.19,1731.81 699.09,1731.81 753.34,1732.19 775.6,1732.31 802.66,1732.58 828.63,1732.86 855.69,1732.99 883.99,1732.72 912.06,1732.59 941.14,1732.53 968.26,1732.84 394.17,1734.02 989.84,1734 1010.12,1734.05 1051.93,1733.86 3789.12,1735.09 4235.12,1739.5 1165.28,1741.43 3905.57,1741.22 4637.16,1741.38 1072.54,1742.18 3969.02,1742.28 4558.41,1741.71 4594.72,1742.3 3999.13,1743.2 4038.54,1743.3 4058.77,1743.3 4115.41,1743.25 4135.34,1743.1 4154.92,1742.86 4533.05,1742.96 4616.01,1743.3 4096.56,1743.59 4173.42,1743.53 4194.61,1743.59 4270.57,1744.02 4304.47,1744.02 4338.37,1744.02 4372.27,1744.02 4406.17,1744.02 4440.07,1744.02 4473.97,1744.02 4507.87,1743.91 348.78,1746.04 375.54,1745.56 1093.3,1745.62 717.49,1748.55 1042.84,1749.4 1020.78,1749.51 1181.98,1749.64 873.08,1755.92 1112.93,1756.15 1153.8,1757.07 750.51,1774.8 3976.68,1777.43 3999.65,1777.07 4040.21,1777.27 4098.52,1777.24 4119.19,1776.99 4140.68,1777.09 4159.76,1777.16 4180.22,1777.39 4200.63,1777.49 4274.75,1777.05 4308.65,1777.05 4342.55,1777.05 4376.45,1777.05 4410.35,1777.05 4444.25,1777.05 4532.39,1777.33 4553.43,1777.25 4626.46,1777.09 3930.79,1778.43 4058.26,1777.78 4503.5,1778.35 4600.33,1777.6 1113.06,1779.42 3904.42,1779.14 4226.45,1779.32 4249.75,1779.19 4575.91,1779.04 717.49,1782.45 1150.52,1784.73 3846.32,1789.77 3866.47,1790.19 1132.66,1792.27 4485.83,1793.88 4038.24,1795.25 3980.79,1796.23 4629.21,1797.37 775.59,1799.87 1257,1805 3836.36,1804.77 3854.44,1804.55 3998.74,1805.17 4057.28,1805.63 750.51,1808.7 717.49,1816.35 1224.94,1826.28 1251.58,1826.94 3986.7,1828.85 750.51,1842.6 717.49,1850.25 750.51,1876.5 717.49,1884.15 750.51,1910.4 717.49,1918.05 765.13,1938.36 686.54,1952.61 787.67,1960.75 670.26,1987.14 797.79,1997.25 681.86,2031.53 783.97,2034.5 754.62,2055.22 714.66,2055.72
  other v3: 1295.97,1525.35 1345.58,1525.35 1395.18,1525.35 1254.04,1567.28 1295.97,1567.28 1345.58,1567.28 1395.18,1567.28 1437.11,1567.28 1254.04,1616.88 1295.97,1616.88 1345.58,1616.88 1395.18,1616.88 1437.11,1616.88 1254.04,1666.49 1295.97,1666.49 1345.58,1666.49 1395.18,1666.49 1437.11,1666.49 1295.97,1708.42 1345.58,1708.42 1395.18,1708.42 3552.76,1768.7 3602.36,1768.7 3651.97,1768.7 3510.83,1810.63 3552.76,1810.63 3602.36,1810.63 3651.97,1810.63 3693.9,1810.63 3510.83,1860.24 3552.76,1860.24 3602.36,1860.24 3651.97,1860.24 3693.9,1860.24 3510.83,1909.84 3552.76,1909.84 3602.36,1909.84 3651.97,1909.84 3693.9,1909.84 3552.76,1951.77 3602.36,1951.77 3651.97,1951.77
  other v4: 3577.56,2899.61 3627.56,2899.6
NetANT1_1: ANT1.1 C46.2 L5.2 | length 100.8
  Top Layer w6.5: L5.2@4543.8,1760.43 C46.2@4574.18,1760.43 ; C46.2@4576.77,1760.35 4647.18,1760.35
NetANT2_1: ANT2.1 C86.2 L11.2 | length 103
  Top Layer w6.5: ANT2.1@289.5,1715.76 L11.2@392.46,1715.77
NetC12_2: C12.2 R8.1 U1.12 | length 1210.7
  Top Layer w8: U1.12@3736.22,1968.5 3749.83,1982.11 3749.83,2007.61 3762.07,2019.84 v1(3769.53,2019.84)
  Bottom Layer w8: C12.2@3724.43,1052.77 C12.2@3724.6,1052.59 R8.1@3682.93,1052.59 3683.42,1053.08 3683.42,1210.83 3863.46,1390.87 3863.46,1563.14 3842.4,1584.2 3842.4,1606.31 3749.02,1699.69 3749.02,1704.16 3747.36,1705.82 3747.36,1997.67 v1(3769.53,2019.84)
NetC13_2: C13.2 R7.1 U1.11 | length 1305.6
  Top Layer w8: U1.11@3737.67,1950.26 3750.35,1950.26 ; 3751.8,1951.71 3764.67,1964.58 3765.7,1965.87 3765.7,1989.41 3770.39,1994.09 v1(3774.61,1994.09) ; v1@4061.86,1088.97 R7.1@4061.86,1052.22 C13.2@4104.69,1052.22
  Bottom Layer w8: v1(3774.61,1994.09) 3795.8,2015.29 3931.42,2015.29 4077.67,1869.04 4077.67,1107.41 4061.83,1091.57 v1(4061.83,1089.01)
NetC14_2: C14.2 R6.1 U1.10 | length 1985.2
  Top Layer w8: v1(3267.6,1480.86) 3736.94,1480.86 3738.45,1479.35 3835.64,1479.35 v1@4023.61,1560.8 ; U1.10@3736.22,1929.13 3748.91,1929.13 3764.63,1940.26 3769.12,1944.75 v1(3799.35,1982.46)
  Bottom Layer w8: C14.2@3208.81,1053.17 R6.1@3164.74,1053.17 3164.74,1378 v1(3267.6,1480.86) ; v1(3799.35,1982.46) 3816.31,1999.42 3924.85,1999.42 4018.55,1905.72 v1(4018.55,1560.03)
NetC15_2: C15.2 R5.1 U1.9 | length 1162.3
  Top Layer w8: U1.9@3736.22,1909.45 3754.64,1909.45 3762.78,1918.49 3764.12,1919.7 v1(3786.33,1928.15) ; v1(3975.8,1086.56) 3975.42,1086.18 R5.1@3975.42,1052.22 C15.2@4018.55,1052.22
  Bottom Layer w8: v1(3786.33,1928.15) 3816.39,1958.21 3898.98,1958.21 3950,1907.19 3950,1799.43 3950,1740.35 3950,1685.11 3975.8,1659.3 v1(3975.8,1086.56)
NetC16_2: C16.2 R4.1 U1.8 | length 1083
  Top Layer w8: U1.8@3736.22,1889.76 3737.14,1890.69 3758.33,1890.69 3772.97,1905.33 3793.92,1905.33 3814.45,1925.86 v1(3814.45,1927.1)
  Bottom Layer w8: v1(3814.45,1927.1) 3816.26,1925.29 3822.7,1925.29 3885.32,1862.67 3885.32,1718.04 3914.27,1689.09 3923.57,1689.09 3949.41,1663.25 3949.41,1352.9 3935.11,1338.6 3935.11,1053.9 R4.1@3933.44,1052.22 C16.2@3975.42,1052.22
NetC17_1: C17.1 R9.1 U1.14 | length 1219.9
  Top Layer w8: v1(3641.34,1090.83) 3640.76,1090.25 R9.1@3640.76,1052.59 C17.1@3683.42,1052.59 ; U1.14@3690.94,1994.09 3691.44,1994.59 3691.44,2019.84 v1(3709.65,2041.1)
  Bottom Layer w8: v1(3641.34,1090.83) 3641.34,1208.51 3820.25,1387.43 3820.25,1538.55 3801.5,1556.83 3801.5,1603.76 3730.23,1675.03 3719.88,1675.03 3707.81,1687.09 3707.81,1704.16 3717.68,1714.03 3717.68,1940.04 3709.65,1947.26 v1(3709.65,2041.1)
NetC18_2: C18.2 R3.1 U1.7 | length 1060.8
  Top Layer w8: U1.7@3736.22,1870.08 3760.32,1870.08 3776.59,1886.35 3798.72,1886.35 3804.08,1886.35 v1(3817.02,1899.3) ; v1(3889.25,1086.56) R3.1@3889.25,1052.22 C18.2@3932.79,1052.22
  Bottom Layer w8: v1(3817.02,1899.3) 3816.99,1761.79 3890.02,1688.75 3890.02,1664.36 3906.51,1647.87 3923.57,1647.87 3933.53,1637.9 3933.53,1361.72 3888.44,1316.63 3888.44,1159.98 3888.44,1087.36 v1(3889.25,1086.56)
NetC19_2: C19.2 R2.1 U1.6 | length 997
  Top Layer w8: U1.6@3736.22,1850.39 3750.75,1850.39 3753.94,1853.58 3772.95,1853.58 v1(3785.12,1865.75)
  Bottom Layer w8: v1(3785.12,1865.75) 3801.12,1849.76 3801.12,1755.21 3874.15,1682.18 3874.15,1634.07 3917.66,1590.56 3917.66,1368.79 3845.75,1296.88 3845.75,1052.61 R2.1@3846.14,1052.22 C19.2@3889.51,1052.22
NetC20_2: C20.2 R1.1 U1.5 | length 991.8
  Top Layer w8: v1(3725.46,1089.49) 3724.87,1088.89 R1.1@3724.87,1052.41 C20.2@3768.5,1052.41 ; U1.5@3736.22,1830.71 3736.47,1830.95 3767.64,1830.95 v1(3767.96,1831.28)
  Bottom Layer w8: v1(3725.46,1089.49) 3725.46,1208.58 3901.79,1384.9 3901.79,1583.98 3872.89,1612.88 3858.27,1612.88 3767.96,1703.19 v1(3767.96,1831.28)
NetC29_2: C29.2 R18.1 U1.43 | length 781.6
  Top Layer w8: v1(3553.69,1089.85) 3553.69,1053.69 R18.1@3554.61,1052.78 C29.2@3597.41,1052.78 ; v1@3609.92,1695.3 v1(3610.92,1696.3) ; v1@3612.2,1703.58 U1.43@3612.2,1726.38
  Bottom Layer w8: v1(3553.69,1089.85) 3553.69,1284.06 3667.6,1397.97 3667.6,1626.22 3629.4,1664.42 3629.4,1677.83 v1(3610.92,1696.3)
NetC30_2: C30.2 R15.1 U1.38 | length 786.6
  Top Layer w8: v1(3484.14,1615.37) 3505.14,1636.38 3505.14,1702.14 3513.78,1710.77 U1.38@3513.78,1726.38
  Bottom Layer w8: C30.2@3382.95,1052.78 R15.1@3341.36,1052.78 3342.55,1053.97 3342.55,1362.41 3461.45,1481.3 3461.45,1592.68 v1(3484.14,1615.37)
NetC31_2: C31.2 R17.1 U1.42 | length 813.7
  Top Layer w8: v1(3384.09,1086.18) 3384.09,1053.48 R17.1@3383.39,1052.78 C31.2@3426.45,1052.78 ; v1@3559.75,1664.58 3561.78,1666.61 3574.19,1666.61 3590.32,1682.75 3590.32,1704.84 3592.52,1707.03 U1.42@3592.52,1726.38
  Bottom Layer w8: v1(3384.09,1086.18) 3384.09,1315.19 3533.46,1464.57 3533.46,1644.58 v1(3557.49,1668.61)
NetC32_2: C32.2 R14.1 U1.37 | length 799.4
  Top Layer w8: v1(3297.01,1086.18) 3297.01,1053.94 R14.1@3296.27,1053.2 C32.2@3340.52,1053.2 ; v1(3466.5,1636.15) 3489.27,1658.92 3489.27,1709.29 3494.09,1714.11 U1.37@3494.09,1726.38
  Bottom Layer w8: v1(3297.01,1086.18) 3297.01,1364.27 3445.57,1512.83 3445.57,1615.22 v1(3466.5,1636.15)
NetC33_2: C33.2 R16.1 U1.41 | length 800.4
  Top Layer w8: v1(3568.51,1691.47) 3572.83,1695.79 U1.41@3572.83,1726.38
  Bottom Layer w8: C33.2@3554.46,1052.78 R16.1@3511.35,1052.78 3511.35,1265.54 3626.2,1380.38 3626.2,1630.82 3607.55,1649.47 3607.55,1662.19 3578.26,1691.47 v1(3568.51,1691.47) v1@3568.51,1686.73
NetC34_2: C34.2 R13.1 U1.32 | length 1594.4
  Top Layer w8: v1(3316.14,1446.8) 3833.6,1446.8 3956.39,1324.02 v1(4018.88,1324.02) ; v1(3408.97,1830.54) U1.32@3468.5,1830.71
  Bottom Layer w8: v1(3316.14,1446.8) 3395.3,1525.97 3395.3,1639.37 3425.04,1669.1 3463.22,1709.7 3463.22,1781.29 v1@3407.38,1830.95 ; v1@4017.63,1321.09 R13.1@4018.88,1052.22 C34.2@4061.83,1052.22
NetC39_1: C39.1 C43.1 L4.2 | length 251.7
  Top Layer w6.5: L4.2@3961.83,1760.37 C43.1@4213.52,1760.37
NetC39_2: C39.2 J4.1 | length 253.9
  Top Layer w6.5: J4.1@4215.5,1484.25 C39.2@4215.5,1738.19
NetC40_1: C40.1 L2.2 | length 23
  Top Layer w6.5: C40.1@3815.85,1705 L2.2@3815.85,1727.99
NetC42_2: C42.2 L3.1 L6.2 | length 60.2
  Top Layer w6.5: L6.2@3856.83,1772.3 3868.95,1772.3 cw(c3868.95,1760.71) 3877.14,1768.91 cw(c3869.37,1761.14) 3880.36,1761.14 L3.1@3880.36,1760.3 3880.36,1759.94 cw(c3869.37,1759.94) 3877.14,1752.17 cw(c3870.22,1759.09) 3870.22,1749.3 C42.2@3857.35,1749.3
NetC43_2: C43.2 C45.2 L5.1 | length 275.7
  Top Layer w6.5: C43.2@4238,1760.54 C45.2@4482.36,1760.54 ; C45.2@4485.52,1760.43 L5.1@4516.84,1760.43
NetC44_2: C44.2 L3.2 L4.1 | length 38.2
  Top Layer w6.5: L3.2@3902.01,1760.37 L4.1@3940.17,1760.37
NetC49_1: C49.1 U6.3 | length 99.6
  Top Layer w8: v1(3144.02,2235.27) U6.3@3144.02,2274.38
  Bottom Layer w8: v1(3144.02,2235.27) 3144.02,2176.02 C49.1@3144.87,2175.16
NetC51_1: C51.1 U6.2 | length 105.1
  Top Layer w8: v1@3118.43,2235.82 U6.2@3118.43,2274.38
  Top Layer w10: v1(3117.88,2235.27) v1@3118.43,2235.82
  Bottom Layer w8: C51.1@3104.33,2175.16 3117.88,2188.71 v1(3117.88,2235.27)
NetC52_2: C52.2 R32.1 U7.12 | length 616.5
  Top Layer w8: U7.12@1211.72,1508.61 1198.74,1508.61 1180.62,1490.5 1180.62,1456.79 1169.84,1446.02 1169.84,1342.91 1301.87,1210.88 1301.87,1035.88 1301.78,1035.78 1301.78,1027.25 R32.1@1293.97,1019.44 1293.97,1019.14 1337.67,1019.14 C52.2@1337.97,1019.44
NetC53_2: C53.2 R31.1 U7.11 | length 657.3
  Top Layer w8: U7.11@1211.72,1528.3 1195.97,1528.3 1164.75,1497.07 1164.75,1463.37 1144.71,1443.33 1144.71,1127.36 1124.13,1106.78 1124.13,1060.22 1132.22,1052.13 1174.28,1052.13 R31.1@1206.97,1019.44 C53.2@1250.97,1019.44
NetC54_2: C54.2 R30.1 U7.10 | length 656.6
  Top Layer w8: C54.2@1078.97,1019.44 R30.1@1034.97,1019.44 1064.08,1048.56 1064.08,1385.15 1148.88,1469.95 1148.88,1503.65 1193.21,1547.98 U7.10@1211.72,1547.98
NetC55_1: C55.1 R33.1 U7.14 | length 560.7
  Top Layer w8: U7.14@1256.99,1483.02 1256.99,1281.51 1360.18,1178.32 1360.18,1106.83 1360.13,1106.78 1360.13,1041.28 1370.22,1031.19 1374.16,1031.19 1381.97,1023.38 R33.1@1381.97,1019.44 C55.1@1424.97,1019.44
NetC56_2: C56.2 R29.1 U7.9 | length 777.4
  Top Layer w8: C56.2@990.97,1019.44 R29.1@947.97,1019.44 947.97,1047.44 943.28,1052.12 909.08,1052.12 902.13,1059.08 902.13,1202.92 909.08,1209.87 920.07,1209.87 1019.09,1308.9 1019.09,1364.27 1133,1478.18 1133,1510.22 1190.45,1567.67 U7.9@1211.72,1567.67
NetC57_2: C57.2 R28.1 U7.8 | length 776.7
  Top Layer w8: C57.2@903.97,1019.44 R28.1@860.97,1019.44 860.97,1184.21 902.51,1225.75 913.49,1225.75 1003.22,1315.48 1003.22,1374.14 1117.13,1488.05 1117.13,1516.8 1187.68,1587.35 U7.8@1211.72,1587.35
NetC58_2: C58.2 R27.1 U7.7 | length 716.4
  Top Layer w8: v1(1152.38,1582.46) 1154.94,1582.46 1164.52,1592.04 1169.84,1592.04 1184.84,1607.04 U7.7@1211.72,1607.04
  Bottom Layer w8: v1(1152.38,1582.46) 1152.38,1519.35 1250.97,1420.76 R27.1@1250.97,1019.44 C58.2@1293.97,1019.44
NetC59_2: C59.2 R26.1 U7.6 | length 768.4
  Top Layer w8: v5@1161.31,1612.64 1172.06,1623.4 1189.8,1623.4 1193.13,1626.72 U7.6@1211.72,1626.72
  Bottom Layer w8: v5(1159.31,1613.64) 1172.98,1599.98 1172.98,1522.28 1286.35,1408.91 1286.35,1374.32 1337.97,1322.7 R26.1@1337.97,1019.44 C59.2@1381.97,1019.44
NetC60_2: C60.2 R25.1 U7.5 | length 802
  Top Layer w8: v1@1181.27,1641.5 1183.83,1641.5 1188.74,1646.41 U7.5@1211.72,1646.41
  Bottom Layer w8: v1(1181.27,1644) 1188.85,1636.42 1188.85,1535.93 1306.03,1418.76 1306.03,1392.79 1306.03,1389.75 1306.03,1377.08 1353.84,1329.27 1353.84,1267.71 1424.97,1196.59 R25.1@1424.97,1019.44 C60.2@1468.97,1019.44
NetC69_2: C69.2 R39.1 U7.38 | length 1399.4
  Top Layer w8: U7.38@1434.16,1750.74 1434.16,1767.88 1458.09,1791.81 v1(1458.09,1842.56)
  Bottom Layer w8: v1(1458.09,1842.56) 1458.09,1834.98 1444.06,1820.95 1428.95,1820.95 1414.47,1806.47 1414.47,1750.74 1393.87,1730.13 1286.97,1730.13 1232.32,1675.48 1232.32,1543.54 1339.2,1436.66 1339.13,1436.66 1339.13,1388.89 1385.59,1342.42 1385.59,1308.59 1488.15,1206.03 1618.02,1206.03 1622.36,1201.69 1622.36,1121.98 1691.97,1052.37 R39.1@1691.97,1019.44 C69.2@1734.97,1019.44
NetC70_2: C70.2 R42.1 U7.43 | length 961.5
  Top Layer w8: v1(1335.54,1776.34) 1335.73,1776.14 U7.43@1335.73,1750.74
  Bottom Layer w8: C70.2@1121.73,1019.44 R42.1@1078.97,1019.44 1078.97,1189.13 1112.68,1222.83 1112.68,1455.88 1131.78,1474.98 1131.78,1623.64 1270.02,1761.88 1321.09,1761.88 v1(1335.54,1776.34)
NetC71_2: C71.2 R38.1 U7.37 | length 1395.1
  Top Layer w8: U7.37@1453.84,1750.74 1453.84,1757.63 1479.26,1783.04 v1(1479.26,1864.86)
  Bottom Layer w8: C71.2@947.97,1019.44 R38.1@903.97,1019.44 903.45,1019.96 903.45,1296.82 1100.03,1493.4 1100.03,1636.79 1203.33,1740.09 1203.33,1831.83 1236.36,1864.86 v1(1479.26,1864.86)
NetC72_2: C72.2 R41.1 U7.42 | length 1061
  Top Layer w8: U7.42@1355.42,1750.74 1356.14,1751.46 1356.14,1780.92 v1(1360.18,1784.96)
  Bottom Layer w8: C72.2@1034.97,1019.44 R41.1@990.97,1019.44 992.96,1021.43 992.96,1363.88 1115.9,1486.82 1115.9,1630.22 1265.33,1779.65 1309.71,1779.65 1327.01,1796.94 1344.07,1796.94 1356.05,1784.96 v1(1360.18,1784.96)
NetC73_2: C73.2 R37.1 U7.32 | length 816.1
  Top Layer w8: U7.32@1479.43,1646.41 1479.43,1646.48 v1@1525.71,1646.48
  Bottom Layer w8: v1(1528.33,1641.5) 1528.33,1557.74 1779.02,1307.05
  Bottom Layer w10: 1779.02,1307.05 R37.1@1779.02,1019.44 C73.2@1822.87,1019.44
NetC74_2: C74.2 R40.1 U7.41 | length 1234.9
  Top Layer w8: U7.41@1375.1,1750.74 1375.1,1770.75 1380.78,1776.43 1380.78,1795.73 v1(1383.06,1798)
  Bottom Layer w8: v1(1383.06,1798) 1383.06,1750.69 1378.37,1746.01 1280.4,1746.01 1216.45,1682.06 1216.45,1536.96 1323.25,1430.16 1323.25,1382.31 1369.72,1335.85 1369.72,1282.02 1461.58,1190.16 1588.89,1190.16 1605.46,1173.59 R40.1@1605.46,1019.44 C74.2@1649.15,1019.44
NetC79_1: C79.1 C83.1 L10.2 | length 255.1
  Top Layer w6.5: C79.1@733.1,1715.4 787.27,1715.4 L10.2@988.17,1715.4
NetC79_2: C79.2 J11.1 | length 256.2
  Top Layer w6.5: C79.2@734,1738.18 J11.1@734,1994.38
NetC80_1: C80.1 L8.2 | length 21.9
  Top Layer w6.5: L8.2@1133.36,1748.1 C80.1@1133.45,1770
NetC82_2: C82.2 L9.1 L12.2 | length 58.1
  Top Layer w6.5: C82.2@1092.25,1726.45 1081.56,1726.45 ccw(c1081.56,1715.23) 1073.63,1723.16 1072.63,1722.16 ccw(c1079.39,1715.4) L9.1@1069.83,1715.4 ccw(c1079.87,1715.4) 1072.77,1708.3 1073.63,1707.44 ccw(c1081.89,1715.7) 1081.89,1704.02 L12.2@1093.31,1704.02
